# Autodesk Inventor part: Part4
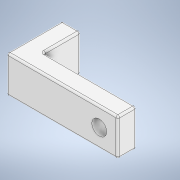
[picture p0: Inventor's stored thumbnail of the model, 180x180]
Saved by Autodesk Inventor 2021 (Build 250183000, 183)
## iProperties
Created: 2025-05
Part Number: Part4
Material: Generic
Document SubType Name: Modeling
Designer: Aaditya
Density: 1 g/cm^3
Appearance: Default
Author: Aaditya
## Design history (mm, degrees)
sketch "Sketch1"
  geometry: L1 (-500, 100)-(100, 100); L2 (100, 100)-(100, -100); L3 (100, -100)-(-500, -100); L4 (-500, -100)-(-500, 100); C1 r 40 at (0, 0); 1 further point
  constraints: 8 end point, 2 parallel, 1 centre point, 1 coincident, 1 horizontal, 1 perpendicular
  dimensions: "d0" = 80 diameter of C1; "d1" = 600 distance of L1.start L1.end; "d2" = 100 distance from line of point (0, 0) L2; "d3" = 100 distance from line of point (0, 0) L3; "d4" = 200 distance of L1.end L2.end
extrude "Extrusion1" new body sketch "Sketch1" distance "d5" = 100; taper "d6" = 0 deg
sketch "Sketch2"
  geometry: L1 (0, 0)-(0, 200) reference; L2 (-200, 200)-(0, 200); L3 (0, 200)-(0, 0); L4 (0, 0)-(-200, 0); L5 (-200, 0)-(-200, 200); 2 further points
  constraints: 8 end point, 2 parallel, 1 horizontal, 1 perpendicular
  dimensions: "d7" = 200 distance of L4.end L2.start; "d8" = 200 distance of L2.start L2.end
extrude "Extrusion2" join sketch "Sketch2" distance "d9" = 100; taper "d10" = 0 deg
fillet "Fillet1" dims "d11" = 10
body "Solid1"
